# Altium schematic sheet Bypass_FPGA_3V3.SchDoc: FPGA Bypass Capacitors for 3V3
size A4; Organization: Altium Limited.; Address1: Level 3, 12a Rodborough Rd; Address2: Frenchs Forest 2086; Address3: NSW; Address4: AUSTRALIA; DocumentNumber: 7; SheetNumber: 7; SheetTotal: 23
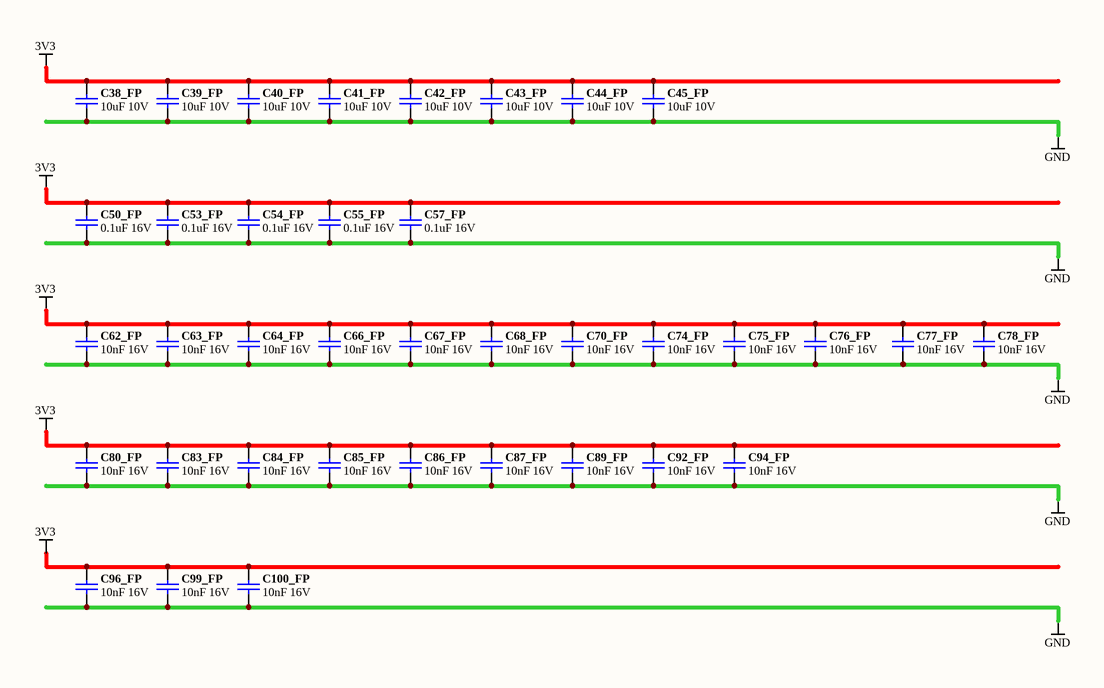
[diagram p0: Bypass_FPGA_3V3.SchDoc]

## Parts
C38_FP  10uF 10V  [CAPC2012-STAR]
C39_FP  10uF 10V  [CAPC2012-STAR]
C40_FP  10uF 10V  [CAPC2012-STAR]
C41_FP  10uF 10V  [CAPC2012-STAR]
C42_FP  10uF 10V  [CAPC2012-STAR]
C43_FP  10uF 10V  [CAPC2012-STAR]
C44_FP  10uF 10V  [CAPC2012-STAR]
C45_FP  10uF 10V  [CAPC2012-STAR]
C50_FP  0.1uF 16V  [CAPC1005-STAR]
C53_FP  0.1uF 16V  [CAPC1005-STAR]
C54_FP  0.1uF 16V  [CAPC1005-STAR]
C55_FP  0.1uF 16V  [CAPC1005-STAR]
C57_FP  0.1uF 16V  [CAPC1005-STAR]
C62_FP  10nF 16V  [CAPC1005-STAR]
C63_FP  10nF 16V  [CAPC1005-STAR]
C64_FP  10nF 16V  [CAPC1005-STAR]
C66_FP  10nF 16V  [CAPC1005-STAR]
C67_FP  10nF 16V  [CAPC1005-STAR]
C68_FP  10nF 16V  [CAPC1005-STAR]
C70_FP  10nF 16V  [CAPC1005-STAR]
C74_FP  10nF 16V  [CAPC1005-STAR]
C75_FP  10nF 16V  [CAPC1005-STAR]
C76_FP  10nF 16V  [CAPC1005-STAR]
C77_FP  10nF 16V  [CAPC1005-STAR]
C78_FP  10nF 16V  [CAPC1005-STAR]
C80_FP  10nF 16V  [CAPC1005-STAR]
C83_FP  10nF 16V  [CAPC1005-STAR]
C84_FP  10nF 16V  [CAPC1005-STAR]
C85_FP  10nF 16V  [CAPC1005-STAR]
C86_FP  10nF 16V  [CAPC1005-STAR]
C87_FP  10nF 16V  [CAPC1005-STAR]
C89_FP  10nF 16V  [CAPC1005-STAR]
C92_FP  10nF 16V  [CAPC1005-STAR]
C94_FP  10nF 16V  [CAPC1005-STAR]
C96_FP  10nF 16V  [CAPC1005-STAR]
C99_FP  10nF 16V  [CAPC1005-STAR]
C100_FP  10nF 16V  [CAPC1005-STAR]

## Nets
3V3: C38_FP.1 C39_FP.1 C40_FP.1 C41_FP.1 C42_FP.1 C43_FP.1 C44_FP.1 C45_FP.1 C50_FP.1 C53_FP.1 C54_FP.1 C55_FP.1 C57_FP.1 C62_FP.1 C63_FP.1 C64_FP.1 C66_FP.1 C67_FP.1 C68_FP.1 C70_FP.1 C74_FP.1 C75_FP.1 C76_FP.1 C77_FP.1 C78_FP.1 C80_FP.1 C83_FP.1 C84_FP.1 C85_FP.1 C86_FP.1 C87_FP.1 C89_FP.1 C92_FP.1 C94_FP.1 C96_FP.1 C99_FP.1 C100_FP.1
GND: C38_FP.2 C39_FP.2 C40_FP.2 C41_FP.2 C42_FP.2 C43_FP.2 C44_FP.2 C45_FP.2 C50_FP.2 C53_FP.2 C54_FP.2 C55_FP.2 C57_FP.2 C62_FP.2 C63_FP.2 C64_FP.2 C66_FP.2 C67_FP.2 C68_FP.2 C70_FP.2 C74_FP.2 C75_FP.2 C76_FP.2 C77_FP.2 C78_FP.2 C80_FP.2 C83_FP.2 C84_FP.2 C85_FP.2 C86_FP.2 C87_FP.2 C89_FP.2 C92_FP.2 C94_FP.2 C96_FP.2 C99_FP.2 C100_FP.2

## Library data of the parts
C38_FP C39_FP C40_FP C41_FP C42_FP C43_FP C44_FP C45_FP = D-101-0087: Capacitor, Ceramic, 10uF 10% 10V 0805 (2012) X5R; Polarity: Non-Polarized
C50_FP C53_FP C54_FP C55_FP C57_FP = D-101-0080: Capacitor, Ceramic, 0.1uF 10% 16V 0402 (1005) X7R; Polarity: Non-Polarized
C62_FP C63_FP C64_FP C66_FP C67_FP C68_FP C70_FP C74_FP C75_FP C76_FP C77_FP C78_FP C80_FP C83_FP C84_FP C85_FP C86_FP C87_FP C89_FP C92_FP C94_FP C96_FP C99_FP C100_FP = D-101-0077: Capacitor, Ceramic, 10nF 10% 16V 0402 (1005) X7R; Polarity: Non-Polarized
